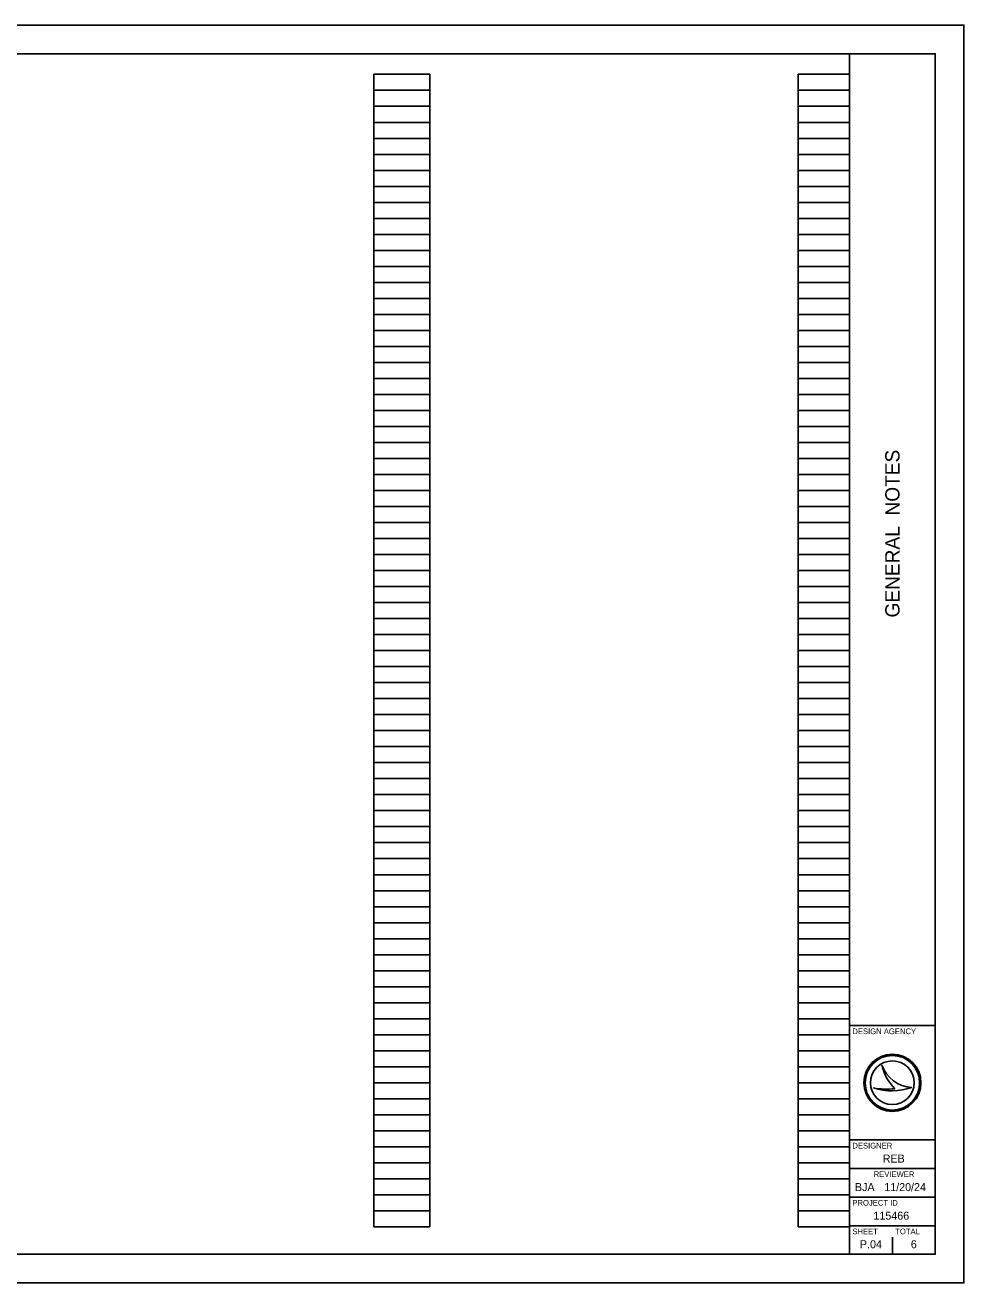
# Model space of a CAD drawing. Extents: x 0 to 34, y 0 to 22.
# Drawn here: x 17.58 to 34, y 0 to 22 of the extents above; entities that cross this region are included whole.
import ezdxf

# ---------------------------------------------------------------- set-up
doc = ezdxf.new("R2010")
doc.units = 0
for name, color, linetype in [('SH_Border', 7, 'Continuous'), ('SH_Cut_Line', 7, 'Continuous'), ('SH_Data', 7, 'Continuous')]:
    doc.layers.add(name, color=color, linetype=linetype)

msp = doc.modelspace()

# ---------------------------------------------------------------- linework, layer by layer
at = {"layer": 'SH_Border'}
for p, q in [((32, 0.5), (32, 21.5)), ((32, 4.5), (33.5, 4.5)), ((32, 2.5), (33.5, 2.5)), ((32, 2), (33.5, 2)), ((32, 1.5), (33.5, 1.5)), ((32, 1), (33.5, 1))]:
    msp.add_line(p, q, dxfattribs=at)
msp.add_lwpolyline([(1.5, 21.5), (33.5, 21.5), (33.5, 0.5), (1.5, 0.5)], close=True, dxfattribs=at)
at = {"layer": 'SH_Cut_Line'}
msp.add_lwpolyline([(0, 0), (34, 0), (34, 22), (0, 22)], close=True, dxfattribs=at)
at = {"layer": 'SH_Data'}
for p, q in [((23.68, 0.98), (23.68, 21.14)), ((23.68, 21.14), (24.66, 21.14)), ((24.66, 0.98), (24.66, 21.14)), ((31.1, 0.98), (31.1, 21.14)), ((31.1, 21.14), (32, 21.14)), ((32, 0.98), (32, 21.14)), ((23.68, 20.86), (24.66, 20.86)), ((31.1, 20.86), (32, 20.86)), ((23.68, 20.58), (24.66, 20.58)), ((31.1, 20.58), (32, 20.58)), ((23.68, 20.3), (24.66, 20.3)), ((31.1, 20.3), (32, 20.3)), ((23.68, 20.02), (24.66, 20.02)), ((31.1, 20.02), (32, 20.02)), ((23.68, 19.74), (24.66, 19.74)), ((31.1, 19.74), (32, 19.74)), ((23.68, 19.46), (24.66, 19.46)), ((31.1, 19.46), (32, 19.46)), ((23.68, 19.18), (24.66, 19.18)), ((31.1, 19.18), (32, 19.18)), ((23.68, 18.9), (24.66, 18.9)), ((31.1, 18.9), (32, 18.9)), ((23.68, 18.62), (24.66, 18.62)), ((31.1, 18.62), (32, 18.62)), ((23.68, 18.34), (24.66, 18.34)), ((31.1, 18.34), (32, 18.34)), ((23.68, 18.06), (24.66, 18.06)), ((31.1, 18.06), (32, 18.06)), ((23.68, 17.78), (24.66, 17.78)), ((31.1, 17.78), (32, 17.78)), ((23.68, 17.5), (24.66, 17.5)), ((31.1, 17.5), (32, 17.5)), ((23.68, 17.22), (24.66, 17.22)), ((31.1, 17.22), (32, 17.22)), ((23.68, 16.94), (24.66, 16.94)), ((31.1, 16.94), (32, 16.94)), ((23.68, 16.66), (24.66, 16.66)), ((31.1, 16.66), (32, 16.66)), ((23.68, 16.38), (24.66, 16.38)), ((31.1, 16.38), (32, 16.38)), ((23.68, 16.1), (24.66, 16.1)), ((31.1, 16.1), (32, 16.1)), ((23.68, 15.82), (24.66, 15.82)), ((31.1, 15.82), (32, 15.82)), ((23.68, 15.54), (24.66, 15.54)), ((31.1, 15.54), (32, 15.54)), ((23.68, 15.26), (24.66, 15.26)), ((31.1, 15.26), (32, 15.26)), ((23.68, 14.98), (24.66, 14.98)), ((31.1, 14.98), (32, 14.98)), ((23.68, 14.7), (24.66, 14.7)), ((31.1, 14.7), (32, 14.7)), ((23.68, 14.42), (24.66, 14.42)), ((31.1, 14.42), (32, 14.42)), ((23.68, 14.14), (24.66, 14.14)), ((31.1, 14.14), (32, 14.14)), ((23.68, 13.86), (24.66, 13.86)), ((31.1, 13.86), (32, 13.86)), ((23.68, 13.58), (24.66, 13.58)), ((31.1, 13.58), (32, 13.58)), ((23.68, 13.3), (24.66, 13.3)), ((31.1, 13.3), (32, 13.3)), ((23.68, 13.02), (24.66, 13.02)), ((31.1, 13.02), (32, 13.02)), ((23.68, 12.74), (24.66, 12.74)), ((31.1, 12.74), (32, 12.74)), ((23.68, 12.46), (24.66, 12.46)), ((31.1, 12.46), (32, 12.46)), ((23.68, 12.18), (24.66, 12.18)), ((31.1, 12.18), (32, 12.18)), ((23.68, 11.9), (24.66, 11.9)), ((31.1, 11.9), (32, 11.9)), ((23.68, 11.62), (24.66, 11.62)), ((31.1, 11.62), (32, 11.62)), ((23.68, 11.34), (24.66, 11.34)), ((31.1, 11.34), (32, 11.34)), ((23.68, 11.06), (24.66, 11.06)), ((31.1, 11.06), (32, 11.06)), ((23.68, 10.78), (24.66, 10.78)), ((31.1, 10.78), (32, 10.78)), ((23.68, 10.5), (24.66, 10.5)), ((31.1, 10.5), (32, 10.5)), ((23.68, 10.22), (24.66, 10.22)), ((31.1, 10.22), (32, 10.22)), ((23.68, 9.94), (24.66, 9.94)), ((31.1, 9.94), (32, 9.94)), ((23.68, 9.66), (24.66, 9.66)), ((31.1, 9.66), (32, 9.66)), ((23.68, 9.38), (24.66, 9.38)), ((31.1, 9.38), (32, 9.38)), ((23.68, 9.1), (24.66, 9.1)), ((31.1, 9.1), (32, 9.1)), ((23.68, 8.82), (24.66, 8.82)), ((31.1, 8.82), (32, 8.82)), ((23.68, 8.54), (24.66, 8.54)), ((31.1, 8.54), (32, 8.54)), ((23.68, 8.26), (24.66, 8.26)), ((31.1, 8.26), (32, 8.26)), ((23.68, 7.98), (24.66, 7.98)), ((31.1, 7.98), (32, 7.98)), ((23.68, 7.7), (24.66, 7.7)), ((31.1, 7.7), (32, 7.7)), ((23.68, 7.42), (24.66, 7.42)), ((31.1, 7.42), (32, 7.42)), ((23.68, 7.14), (24.66, 7.14)), ((31.1, 7.14), (32, 7.14)), ((23.68, 6.86), (24.66, 6.86)), ((31.1, 6.86), (32, 6.86)), ((23.68, 6.58), (24.66, 6.58)), ((31.1, 6.58), (32, 6.58)), ((23.68, 6.3), (24.66, 6.3)), ((31.1, 6.3), (32, 6.3)), ((23.68, 6.02), (24.66, 6.02)), ((31.1, 6.02), (32, 6.02)), ((23.68, 5.74), (24.66, 5.74)), ((31.1, 5.74), (32, 5.74)), ((23.68, 5.46), (24.66, 5.46)), ((31.1, 5.46), (32, 5.46)), ((23.68, 5.18), (24.66, 5.18)), ((31.1, 5.18), (32, 5.18)), ((23.68, 4.9), (24.66, 4.9)), ((31.1, 4.9), (32, 4.9)), ((23.68, 4.62), (24.66, 4.62)), ((31.1, 4.62), (32, 4.62)), ((23.68, 4.34), (24.66, 4.34)), ((31.1, 4.34), (32, 4.34)), ((23.68, 4.06), (24.66, 4.06)), ((31.1, 4.06), (32, 4.06)), ((23.68, 3.78), (24.66, 3.78)), ((31.1, 3.78), (32, 3.78)), ((32.567, 3.81), (32.567, 3.81)), ((23.68, 3.5), (24.66, 3.5)), ((31.1, 3.5), (32, 3.5)), ((32.417, 3.41), (32.417, 3.41)), ((32.75, 3.5), (32.75, 3.5)), ((33.087, 3.419), (33.087, 3.419)), ((23.68, 3.22), (24.66, 3.22)), ((31.1, 3.22), (32, 3.22)), ((23.68, 2.94), (24.66, 2.94)), ((31.1, 2.94), (32, 2.94)), ((23.68, 2.66), (24.66, 2.66)), ((31.1, 2.66), (32, 2.66)), ((23.68, 2.38), (24.66, 2.38)), ((31.1, 2.38), (32, 2.38)), ((23.68, 2.1), (24.66, 2.1)), ((31.1, 2.1), (32, 2.1)), ((23.68, 1.82), (24.66, 1.82)), ((31.1, 1.82), (32, 1.82)), ((23.68, 1.54), (24.66, 1.54)), ((31.1, 1.54), (32, 1.54)), ((23.68, 1.26), (24.66, 1.26)), ((31.1, 1.26), (32, 1.26)), ((23.68, 0.98), (24.66, 0.98)), ((31.1, 0.98), (32, 0.98)), ((32.375, 0.675), (32.375, 0.675)), ((32.75, 0.5), (32.75, 0.8))]:
    msp.add_line(p, q, dxfattribs=at)
for radius in [0.5, 0.477, 0.477, 0.382]:
    msp.add_circle((32.75, 3.5), radius, dxfattribs=at)
for centre, radius, start, end in [((33.116, 3.998), 0.58, 198.9257, 198.9319), ((33.347, 3.97), 0.796, 191.6379, 191.6421), ((33.116, 3.998), 0.58, 198.9319, 267.1657), ((33.347, 3.97), 0.796, 191.6421, 226.0947), ((32.739, 4.37), 1.013, 251.4576, 290.0832), ((32.648, 4.654), 1.266, 259.4964, 259.4995), ((32.739, 4.37), 1.013, 251.4527, 251.4576), ((32.648, 4.654), 1.266, 259.4995, 276.6672)]:
    msp.add_arc(centre, radius, start, end, dxfattribs=at)

# ---------------------------------------------------------------- texts
msp.add_text('GENERAL  NOTES', height=0.25, rotation=90, dxfattribs=at).set_placement((32.875, 11.638))
for s, height, p in [('DESIGN AGENCY', 0.1, (32.05, 4.35)), ('DESIGNER', 0.1, (32.05, 2.35)), ('REB', 0.14, (32.581, 2.105)), ('REVIEWER', 0.1, (32.422, 1.85)), ('BJA', 0.14, (32.095, 1.605)), ('11/20/24', 0.14, (32.608, 1.605)), ('PROJECT ID', 0.1, (32.05, 1.35)), ('115466', 0.14, (32.419, 1.105)), ('SHEET', 0.1, (32.05, 0.85)), ('TOTAL', 0.1, (32.8, 0.85)), ('P.04', 0.14, (32.182, 0.605)), ('6', 0.14, (33.073, 0.605))]:
    msp.add_text(s, height=height, dxfattribs=at).set_placement(p)

doc.saveas('drawing.dxf')
